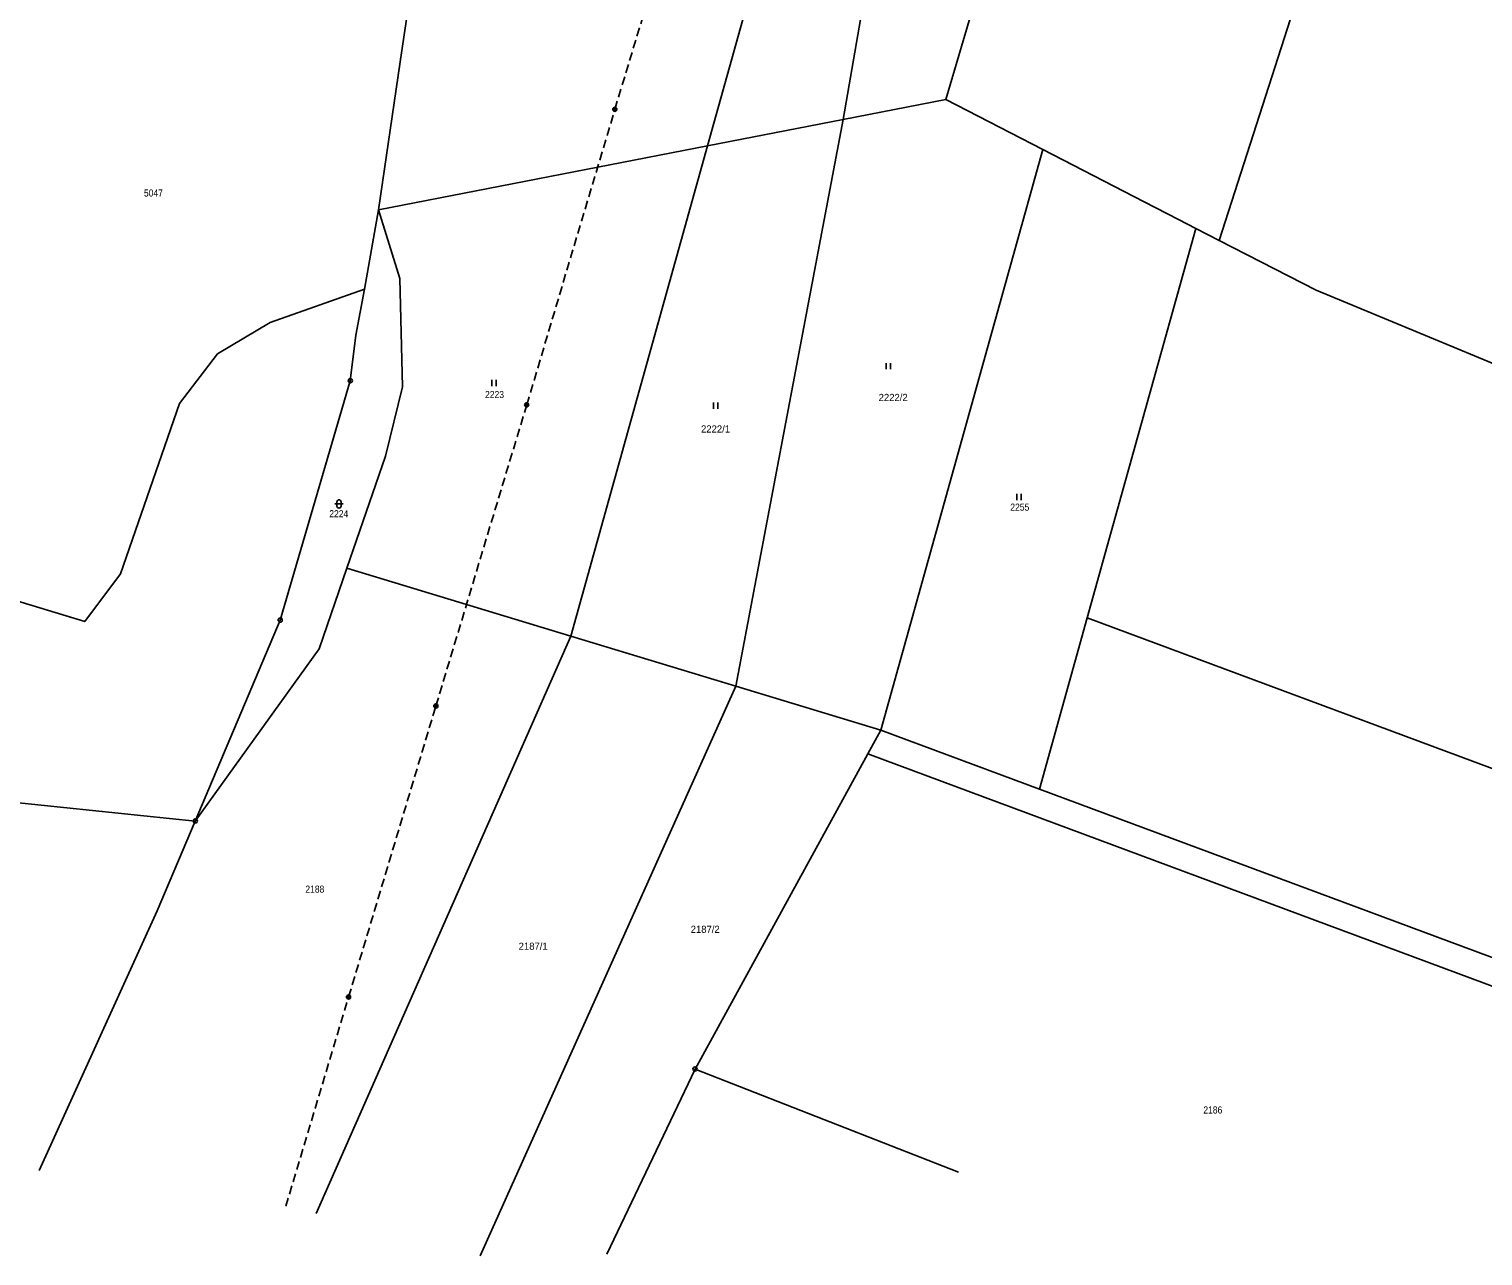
# Model space of a CAD drawing. Extents: x -665688 to -664583, y -1006118 to -1004927.
# Drawn here: x -665404.3 to -665055.9, y -1005939.6 to -1005645.6 of the extents above; entities that cross this region are included whole.
import ezdxf
from ezdxf.enums import TextEntityAlignment as Align

# ---------------------------------------------------------------- set-up
doc = ezdxf.new("R2010")
doc.units = 0
doc.header["$LTSCALE"] = 0.68
doc.linetypes.add('MEDIUM_DASHED', pattern=[4.5, 3, -1.5])
for name, color, linetype, lineweight in [('1', 7, 'Continuous', 25), ('12', 7, 'MEDIUM_DASHED', 25), ('13', 7, 'Continuous', 25), ('24', 7, 'Continuous', 25), ('25', 7, 'Continuous', 25), ('26', 7, 'Continuous', 25)]:
    doc.layers.add(name, color=color, linetype=linetype, lineweight=lineweight)
doc.layers.add('18', color=7, linetype='Continuous')

msp = doc.modelspace()

# ---------------------------------------------------------------- linework, layer by layer
at = {"layer": '1'}
for p, q in [((-665223.62, -1005608.84), (-665241.69, -1005673.6)), ((-665241.69, -1005673.6), (-665320.52, -1005688.93)), ((-665241.69, -1005673.6), (-665274.47, -1005791.07)), ((-665161.35, -1005674.5), (-665200.17, -1005813.59)), ((-665320.52, -1005688.93), (-665315.47, -1005705.35)), ((-665150.75, -1005786.68), (-665124.72, -1005693.36)), ((-665315.47, -1005705.35), (-665314.84, -1005731.36)), ((-665314.84, -1005731.36), (-665318.91, -1005747.93)), ((-665318.91, -1005747.93), (-665328.15, -1005774.8)), ((-665334.78, -1005794.1), (-665328.15, -1005774.8)), ((-665328.15, -1005774.8), (-665274.47, -1005791.07)), ((-665162.2, -1005827.71), (-665150.75, -1005786.68)), ((-665150.75, -1005786.68), (-664981.63, -1005849.59)), ((-665364.46, -1005835.39), (-665334.78, -1005794.1)), ((-665274.47, -1005791.07), (-665335.52, -1005929.46)), ((-665200.17, -1005813.59), (-665162.2, -1005827.71)), ((-665029.87, -1005883.86), (-665203.33, -1005819.32)), ((-664992.8, -1005890.73), (-665162.2, -1005827.71)), ((-665244.72, -1005894.81), (-665265.85, -1005939.16)), ((-665244.72, -1005894.81), (-665181.61, -1005919.53))]:
    msp.add_line(p, q, dxfattribs=at)
for points in [[(-665149.48, -1005588.12), (-665092.38, -1005613.01), (-665119.12, -1005696.24)], [(-665198.65, -1005606.34), (-665209.26, -1005667.29), (-665234.94, -1005803.05), (-665296.22, -1005939.6)], [(-665184.65, -1005662.51), (-665209.26, -1005667.29), (-665241.69, -1005673.6)], [(-665323.94, -1005707.89), (-665346.55, -1005715.92), (-665359.1, -1005723.44), (-665368.23, -1005735.3), (-665382.37, -1005776.17), (-665390.96, -1005787.59), (-665445.72, -1005770.98)], [(-665200.17, -1005813.59), (-665234.94, -1005803.05), (-665274.47, -1005791.07)], [(-665200.17, -1005813.59), (-665203.33, -1005819.32), (-665244.72, -1005894.81)], [(-665481.79, -1005831.46), (-665468.84, -1005832.94), (-665450.28, -1005829.35), (-665419.93, -1005829.7), (-665364.46, -1005835.39)]]:
    msp.add_lwpolyline(points, dxfattribs=at)
at = {"layer": '12'}
msp.add_lwpolyline([(-665342.78, -1005927.71), (-665327.73, -1005877.55), (-665306.81, -1005807.8), (-665285.04, -1005735.65), (-665263.93, -1005664.85), (-665247.23, -1005609.54)], dxfattribs=at)
at = {"layer": '13'}
for p, q in [((-665164.55, -1005594.86), (-665184.65, -1005662.51)), ((-665315.35, -1005653.48), (-665309.42, -1005612.82)), ((-665320.52, -1005688.93), (-665315.35, -1005653.48)), ((-665184.65, -1005662.51), (-665161.35, -1005674.5)), ((-665137.1, -1005686.99), (-665161.35, -1005674.5)), ((-665323.94, -1005707.89), (-665320.52, -1005688.93)), ((-665119.12, -1005696.24), (-665124.72, -1005693.36)), ((-665095.93, -1005708.18), (-665119.12, -1005696.24)), ((-665325.95, -1005718.96), (-665323.94, -1005707.89)), ((-665025.11, -1005737.55), (-665095.93, -1005708.18)), ((-665327.32, -1005729.86), (-665325.95, -1005718.96)), ((-665344.11, -1005787.23), (-665327.32, -1005729.86)), ((-665364.46, -1005835.39), (-665344.11, -1005787.23)), ((-665373.56, -1005856.92), (-665364.46, -1005835.39)), ((-665401.9, -1005919.15), (-665373.56, -1005856.92))]:
    msp.add_line(p, q, dxfattribs=at)
msp.add_lwpolyline([(-665124.72, -1005693.36), (-665128.84, -1005691.24), (-665137.1, -1005686.99)], dxfattribs=at)
at = {"layer": '24'}
for centre, radius in [((-665327.32, -1005729.86), 0.5), ((-665327.32, -1005729.86), 0.032), ((-665344.11, -1005787.23), 0.5), ((-665344.11, -1005787.23), 0.032), ((-665364.46, -1005835.39), 0.5), ((-665364.46, -1005835.39), 0.032), ((-665244.72, -1005894.81), 0.5), ((-665244.72, -1005894.81), 0.032)]:
    msp.add_circle(centre, radius, dxfattribs=at)
at = {"layer": '25'}
for p, q in [((-665198.917, -1005727.125), (-665198.917, -1005725.625)), ((-665197.883, -1005727.125), (-665197.883, -1005725.625)), ((-665293.407, -1005731.175), (-665293.407, -1005729.675)), ((-665292.373, -1005731.175), (-665292.373, -1005729.675)), ((-665240.267, -1005736.595), (-665240.267, -1005735.095)), ((-665239.233, -1005736.595), (-665239.233, -1005735.095)), ((-665331.01, -1005759.4), (-665329.01, -1005759.4)), ((-665330.51, -1005759.9), (-665330.51, -1005758.9)), ((-665329.51, -1005758.9), (-665329.51, -1005759.9)), ((-665167.607, -1005758.505), (-665167.607, -1005757.005)), ((-665166.573, -1005758.505), (-665166.573, -1005757.005))]:
    msp.add_line(p, q, dxfattribs=at)
for centre, start, end in [((-665330.01, -1005758.9), 0.101, 180.00143), ((-665330.01, -1005759.9), 180.10243, 0.00286)]:
    msp.add_arc(centre, 0.5, start, end, dxfattribs=at)
at = {"layer": '26'}
for centre, radius in [((-665263.93, -1005664.85), 0.5), ((-665263.93, -1005664.85), 0.3), ((-665263.93, -1005664.85), 0.15), ((-665285.04, -1005735.65), 0.5), ((-665285.04, -1005735.65), 0.3), ((-665285.04, -1005735.65), 0.15), ((-665306.81, -1005807.8), 0.5), ((-665306.81, -1005807.8), 0.3), ((-665306.81, -1005807.8), 0.15), ((-665327.73, -1005877.55), 0.5), ((-665327.73, -1005877.55), 0.3), ((-665327.73, -1005877.55), 0.15)]:
    msp.add_circle(centre, radius, dxfattribs=at)

# ---------------------------------------------------------------- texts
at = {"layer": '18', "width": 0.9}
for s, p in [('5047', (-665374.4895, -1005685.73)), ('2223', (-665292.7595, -1005734.02)), ('2255', (-665166.8995, -1005761.01)), ('2224', (-665330.0795, -1005762.59)), ('2188', (-665335.8095, -1005852.55)), ('2186', (-665120.6495, -1005905.47))]:
    msp.add_text(s, height=1.7, dxfattribs=at).set_placement(p, align=Align.CENTER)
at = {"layer": '18'}
for s, p in [('2222/2', (-665197.2395, -1005734.72)), ('2222/1', (-665239.7995, -1005742.28)), ('2187/2', (-665242.2795, -1005862.18)), ('2187/1', (-665283.4995, -1005866.23))]:
    msp.add_text(s, height=1.7, dxfattribs=at).set_placement(p, align=Align.CENTER)

doc.saveas('drawing.dxf')
